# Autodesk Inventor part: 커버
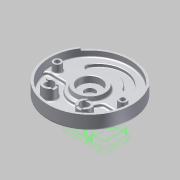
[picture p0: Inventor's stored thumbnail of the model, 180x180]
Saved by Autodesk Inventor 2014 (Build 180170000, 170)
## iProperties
Company: 한국ATC센터
Created: 2015-04
Part Number: 커버
Document SubType Name: Modeling
Designer: KYOUNG IL JANG
Density: 2.71 g/cm^3
Material: 알루미늄 6061
Mass: 1067.78 g
Surface Area: 1019.64 cm^2
Volume: 394.015 cm^3
Appearance: 매끄러움 - 흰색
Author: KYOUNG IL JANG
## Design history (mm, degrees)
sketch "스케치1"
  geometry: L1 (-59, -19)-(-59, 19); L2 (59, 19)-(59, -19); L3 (-41, 19)-(-41, -19); L4 (41, -19)-(41, 19); L5 (38.527, 33.023)-(55.442, 39.179); L6 (-38.527, 33.023)-(-55.442, 39.179); C1 r 90 at (0, 0); C2 r 95 at (0, 0); A1 r 59 centre (0, 19) between (59, 19) and (-59, 19); A2 r 59 centre (0, -19) between (-59, -19) and (59, -19); A3 r 41 centre (0, -19) between (-41, -19) and (41, -19); A4 r 41 centre (0, 19) between (41, 19) and (-41, 19); 2 further points
  constraints: 12 end point, 12 point on circle, 6 centre point, 4 tangent, 2 parallel, 2 point on line, 1 coincident, 1 horizontal alignment, 1 midpoint, 1 vertical, 1 vertical alignment, 3 other
  dimensions: "d2" = 180 diameter of C1; "d3" = 156 dimension on A2 A1; "d4" = 118 distance between parallel lines of L2 L1; "d5" = 18 distance between parallel lines of L2 L4; "d8" = 190 diameter of C2; "d120" = 140 deg angle of L6 L5; "d121" = 110 deg dimension on A1.centre point (0, 0) L5.end
extrude "돌출1" new body sketch "스케치1" distance "d6" = 14; taper "d7" = 0 deg
extrude "돌출2" join sketch "스케치1" distance "d9" = 13; taper "d10" = 0 deg
extrude "돌출3" cut sketch "스케치1" distance "d11" = 7; taper "d12" = 0 deg
sketch "스케치2"
  geometry: C1 r 11.5 at (0, 0); 1 further point
  constraints: 1 centre point, 1 coincident
  dimensions: "d13" = 23 diameter of C1
extrude "돌출4" cut sketch "스케치2" stored distance "d14" = 7; taper "d15" = 0 deg
fillet "모깎기1"
fillet "모깎기2"
sketch "스케치3"
  geometry: L1 (-73.724, 51.622)-(-77.819, 54.49); L2 (73.724, 51.622)-(77.819, 54.49); L3 (0, 0)-(0, -90); A1 r 95 centre (0, 0) between (-77.819, 54.49) and (77.819, 54.49) reference; A2 r 90 centre (0, 0) between (-73.724, 51.622) and (73.724, 51.622) reference; 1 further point
  constraints: 6 end point, 5 point on circle, 1 point on line, 1 vertical, 1 other
  dimensions: "d16" = 250 deg dimension on L2 L1
extrude "돌출5" join sketch "스케치3" distance "d17" = 5; taper "d18" = 0 deg
hole "구멍1" diameter "d21" = 50; stored, may be unused: countersink angle "d25" = 90 deg, drill point angle "d27" = 0 deg; dims "d19" = 10, "d20" = 10, "d22" = 6, "d23" = 4, "d24" = 2, "d26" = 5
fillet "모깎기3" dims "d28" = 0.3
fillet "모깎기5" dims "d30" = 3
sketch "스케치4"
  geometry: C1 r 35 at (0, 0); C2 r 25 at (0, 0); 1 further point
  constraints: 2 centre point, 1 coincident
  dimensions: "d32" = 70 diameter of C1 (derived); "d36" = 10 radial gap between concentric circles of C1 C2
extrude "돌출6" join sketch "스케치4" distance "d33" = 10; taper "d34" = 0 deg
feature "면 기울기2" dims angle "d37" = 10 deg
chamfer "모따기1" distance "d39" = 1; stored, may be unused: second distance "d40" = 2, angle "d41" = 45 deg
fillet "모깎기7" dims "d42" = 5
sketch "스케치5"
  geometry: L1 (-40.249, -12)-(-89.196, -12); L2 (40.249, -12)-(89.196, -12); A1 r 90 centre (0, 0) between (-89.196, -12) and (89.196, -12) reference; A2 r 42 centre (0, 0) between (-40.249, -12) and (40.249, -12); 1 further point
  constraints: 4 end point, 4 point on circle, 1 centre point, 1 collinear, 1 horizontal, 1 point on line
  dimensions: "d43" = 48 radial gap between concentric circles of A1 A2; "d44" = 12 distance from line of point (0, 0) L1
extrude "돌출7" cut sketch "스케치5" stored distance "d45" = 10; taper "d46" = 0 deg
fillet "모깎기8" dims "d47" = 10
chamfer "모따기2" distance "d49" = 1; stored, may be unused: second distance "d50" = 2, angle "d51" = 45 deg
sketch "스케치7"
  geometry: L1 (36.062, 36.062)-(50.912, 50.912); L2 (-36.062, 36.062)-(-50.912, 50.912); A1 r 72 centre (0, 0) between (50.912, 50.912) and (-50.912, 50.912); A2 r 51 centre (0, 0) between (36.062, 36.062) and (-36.062, 36.062); 1 further point
  constraints: 8 point on circle, 4 end point, 2 centre point, 2 point on line, 1 coincident, 1 horizontal alignment
  dimensions: "d54" = 72 radius of A1; "d55" = 21 radial gap between concentric circles of A1 A2; "d56" = 90 deg angle of L2 L1
extrude "돌출8" join sketch "스케치7" distance "d57" = 5; taper "d58" = 0 deg
fillet "모깎기10" dims "d59" = 5
fillet "모깎기11" dims "d60" = 5
fillet "모깎기12" dims "d61" = 3
sketch "스케치6"
  geometry: C1 r 68 at (0, 0); 1 further point
  constraints: 1 centre point, 1 other
  dimensions: "d119" = 136 diameter of C1
feature "엠보싱1" sketch "스케치6" dims "d62" = 0.5, "d63" = 0
sketch "스케치8"
  geometry: C1 r 9 at (74, 0); C2 r 9 at (-74, 0); A1 r 74 centre (0, 0) between (74, 0) and (-74, 0); 1 further point
  constraints: 3 centre point, 2 horizontal alignment, 2 point on circle, 1 coincident, 1 equal radius
  dimensions: "d64" = 18 diameter of C1; "d65" = 148 diameter of A1
extrude "돌출9" join sketch "스케치8" stored distance "d66" = 5; taper "d67" = 0 deg
sketch "스케치11"
  geometry: C1 r 15 at (40, -52); C2 r 15 at (-40, -52); 1 further point
  constraints: 2 centre point, 1 equal radius, 1 horizontal alignment
  dimensions: "d83" = 52 vertical distance of point (0, 0) C1.centre; "d84" = 80 distance of C2.centre C1.centre; "d85" = 40 horizontal distance of point (0, 0) C1.centre (= 0.5 x d84); "d86" = 30 diameter of C1
extrude "돌출10" join sketch "스케치11" stored distance "d87" = 5; taper "d88" = 0 deg
node "구멍3"
node "구멍5"
hole "구멍6" diameter "d93" = 20; stored, may be unused: countersink angle "d97" = 90 deg, drill point angle "d99" = 118 deg; dims "d91" = 10, "d92" = 10, "d94" = 6, "d95" = 4, "d96" = 2, "d98" = 8
hole "구멍7" diameter "d102" = 20; stored, may be unused: countersink angle "d106" = 90 deg, drill point angle "d108" = 118 deg; dims "d100" = 10, "d101" = 10, "d103" = 6, "d104" = 4, "d105" = 2, "d107" = 8
sketch "스케치13"
  geometry: L1 (6, -13.748)-(6, -8); L2 (6, 8)-(6, 13.748); L3 (-6, -13.748)-(-6, -8); L4 (-6, 8)-(-6, 13.748); L5 (-66.252, -6)-(-72, -6); L6 (-88, -6)-(-93.748, -6); L7 (-66.252, 6)-(-72, 6); L8 (-88, 6)-(-93.748, 6); A1 r 15 centre (0, 0) between (6, -13.748) and (6, 13.748) reference; A2 r 10 centre (0, 0) between (6, -8) and (6, 8) reference; A3 r 15 centre (-80, 0) between (-66.252, -6) and (-93.748, -6) reference; A4 r 10 centre (-80, 0) between (-72, -6) and (-88, -6) reference; 1 further point
  constraints: 16 end point, 16 point on circle, 4 equal length, 3 collinear, 2 point on line, 1 perpendicular, 1 vertical
  dimensions: "d109" = 12 distance between parallel lines of L3 L1; "d110" = 6 distance from line of A1.centre L1 (= 0.5 x d109); "d111" = 12 distance between parallel lines of L7 L5; "d112" = 6 distance from line of A3.centre L5 (= 0.5 x d111)
extrude "돌출12" cut sketch "스케치13" distance "d113" = 3; taper "d114" = 0 deg
fillet "모깎기13" dims "d115" = 3
fillet "모깎기14" dims "d116" = 1
node "솔리드1"
sketch "스케치9"
  geometry: 1 further point
hole "구멍2" sketch "스케치9" diameter "d68" = 11; stored, may be unused: countersink angle "d72" = 90 deg, drill point angle "d74" = 0 deg; dims "d69" = 6, "d70" = 18, "d71" = 11, "d73" = 8
sketch "스케치10"
  geometry: 1 further point
hole "구멍4" sketch "스케치10" diameter "d75" = 11; stored, may be unused: countersink angle "d79" = 90 deg, drill point angle "d81" = 0 deg; dims "d76" = 6, "d77" = 18, "d78" = 11, "d80" = 8
